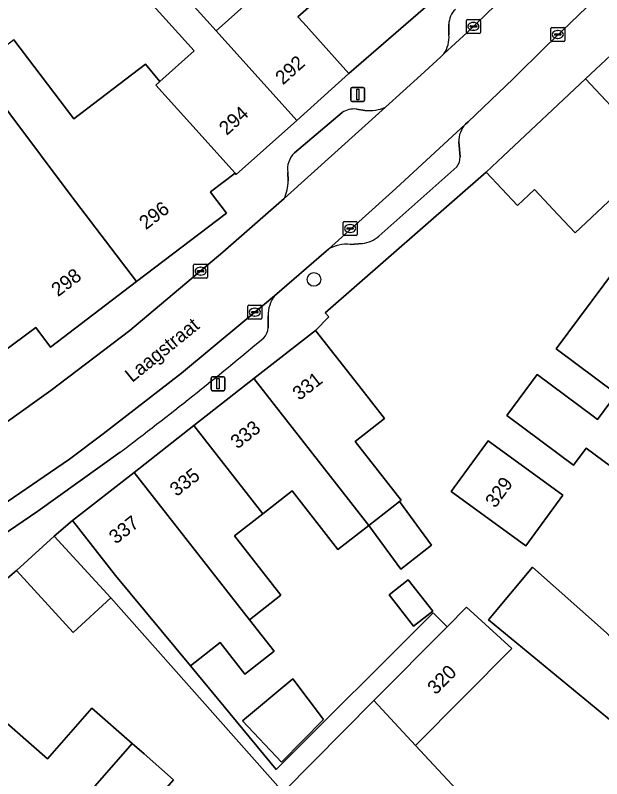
# Model space of a CAD drawing. Extents: x 159217 to 160349, y 381246 to 382172.
# Drawn here: x 160127.1 to 160169.1, y 381674.9 to 381729.7 of the extents above; entities that cross this region are included whole.
import ezdxf

# ---------------------------------------------------------------- set-up
doc = ezdxf.new("R2010")
doc.units = 0
for name, color, linetype in [('IMGEO_Boom', 7, 'Continuous'), ('IMGEO_Erf', 7, 'Continuous'), ('IMGEO_Kolk', 7, 'Continuous'), ('IMGEO_Lichtmast', 7, 'Continuous'), ('IMGEO_Muur', 7, 'Continuous'), ('IMGEO_Openbare_ruimte_label', 7, 'Continuous'), ('IMGEO_Pand', 7, 'Continuous'), ('IMGEO_Pand_nummerreeks', 7, 'Continuous'), ('IMGEO_Parkeervlak_open', 7, 'Continuous'), ('IMGEO_Rijbaan_lokaal_open', 7, 'Continuous'), ('IMGEO_Rioolput', 7, 'Continuous'), ('IMGEO_Voetpad_open', 7, 'Continuous')]:
    doc.layers.add(name, color=color, linetype=linetype)

msp = doc.modelspace()

# ---------------------------------------------------------------- linework, layer by layer
at = {"layer": 'IMGEO_Boom'}
msp.add_circle((160148.48, 381710.751), 0.489, dxfattribs=at)
at = {"layer": 'IMGEO_Erf'}
for points in [[(160137.869, 381732.584), (160141.47, 381728.578), (160145.218, 381731.947)], [(160126.951, 381727.928), (160131.256, 381722.282), (160136.388, 381726.195), (160137.421, 381724.939), (160139.884, 381727.152), (160136.283, 381731.159)], [(160148.841, 381730.954), (160147.331, 381729.597), (160147.702, 381729.183), (160150.987, 381725.528), (160157.187, 381730.928)], [(160173.124, 381719.643), (160167.213, 381714.092), (160165.619, 381715.789), (160165.324, 381716.104), (160164.296, 381717.197), (160163.082, 381716.057), (160160.843, 381718.441), (160149.291, 381708.343), (160149.538, 381708.06), (160148.586, 381707.09), (160151.668, 381703.153), (160153.538, 381700.763), (160151.432, 381699.115), (160154.727, 381694.905), (160154.607, 381694.811), (160156.916, 381691.674), (160154.72, 381689.956), (160152.415, 381693.096), (160150.201, 381691.363), (160146.906, 381695.573), (160144.82, 381693.941), (160142.78, 381692.344), (160146.106, 381688.095), (160143.848, 381686.327), (160145.614, 381684.072), (160143.526, 381682.437), (160141.76, 381684.692), (160139.617, 381683.014), (160145.774, 381675.588), (160157.031, 381686.822), (160158.032, 381685.832), (160159.421, 381687.235), (160162.664, 381684.257), (160155.774, 381677.313), (160168.856, 381663.241)], [(160133.914, 381687.899), (160131.201, 381685.415), (160127.136, 381689.854), (160120.973, 381684.618)], [(160174.403, 381675.265), (160160.99, 381686.315), (160164.149, 381690.107), (160169.471, 381685.396)], [(160121.119, 381682.46), (160121.665, 381683.084), (160125.837, 381679.432), (160129.356, 381676.353), (160132.541, 381679.993), (160135.449, 381677.448), (160136.304, 381676.7), (160138.411, 381674.855), (160135.236, 381671.227), (160138.683, 381668.21), (160141.867, 381671.847), (160143.661, 381670.277), (160140.478, 381666.64), (160142.616, 381664.769), (160148.269, 381671.336), (160145.952, 381673.63), (160146.273, 381673.954), (160133.914, 381687.899)]]:
    msp.add_lwpolyline(points, dxfattribs=at)
for points in [[(160179.535, 381706.233), (160183.549, 381703.251), (160175.817, 381692.844), (160168.008, 381698.646), (160167.1, 381697.424), (160162.304, 381700.987), (160164.487, 381703.924), (160168.5, 381700.942), (160168.821, 381700.704), (160170.183, 381702.538), (160165.85, 381705.758), (160170.946, 381712.616), (160175.279, 381709.396)], [(160166.323, 381695.265), (160163.671, 381691.626), (160158.322, 381695.523), (160160.975, 381699.163)], [(160153.87, 381688.122), (160155.246, 381689.198), (160156.999, 381686.957), (160155.624, 381685.881)], [(160143.347, 381679.066), (160146.967, 381682.092), (160149.172, 381679.183), (160146.155, 381676.119)]]:
    msp.add_lwpolyline(points, close=True, dxfattribs=at)
at = {"layer": 'IMGEO_Kolk'}
for p, q in [((160159.415, 381728.477), (160159.415, 381729.329)), ((160159.49, 381729.403), (160160.342, 381729.403)), ((160160.416, 381729.329), (160160.416, 381728.477)), ((160159.674, 381728.897), (160159.674, 381728.909)), ((160160.112, 381728.86), (160159.714, 381728.86)), ((160159.717, 381728.946), (160160.115, 381728.946)), ((160159.903, 381729.183), (160159.928, 381729.183)), ((160160.158, 381728.909), (160160.158, 381728.897)), ((160165.469, 381727.896), (160165.469, 381728.748)), ((160165.544, 381728.822), (160166.396, 381728.822)), ((160166.47, 381728.748), (160166.47, 381727.896)), ((160160.342, 381728.403), (160159.49, 381728.403)), ((160159.926, 381728.623), (160159.901, 381728.623)), ((160165.728, 381728.316), (160165.728, 381728.328)), ((160166.166, 381728.279), (160165.768, 381728.279)), ((160165.771, 381728.365), (160166.169, 381728.365)), ((160165.957, 381728.602), (160165.982, 381728.602)), ((160166.212, 381728.328), (160166.212, 381728.316)), ((160166.396, 381727.822), (160165.544, 381727.822)), ((160165.98, 381728.042), (160165.955, 381728.042)), ((160139.848, 381710.911), (160139.848, 381711.763)), ((160139.923, 381711.837), (160140.775, 381711.837)), ((160140.849, 381711.763), (160140.849, 381710.911)), ((160140.107, 381711.331), (160140.107, 381711.343)), ((160140.545, 381711.294), (160140.147, 381711.294)), ((160140.15, 381711.38), (160140.548, 381711.38)), ((160140.336, 381711.617), (160140.361, 381711.617)), ((160140.591, 381711.343), (160140.591, 381711.331)), ((160140.775, 381710.837), (160139.923, 381710.837)), ((160140.359, 381711.057), (160140.334, 381711.057)), ((160143.738, 381707.974), (160143.738, 381708.826)), ((160143.813, 381708.9), (160144.665, 381708.9)), ((160144.226, 381708.68), (160144.251, 381708.68)), ((160144.739, 381708.826), (160144.739, 381707.974)), ((160143.997, 381708.394), (160143.997, 381708.406)), ((160144.435, 381708.357), (160144.037, 381708.357)), ((160144.04, 381708.443), (160144.438, 381708.443)), ((160144.249, 381708.12), (160144.224, 381708.12)), ((160144.481, 381708.406), (160144.481, 381708.394)), ((160144.665, 381707.9), (160143.813, 381707.9))]:
    msp.add_line(p, q, dxfattribs=at)
for points in [[(160159.415, 381728.477), (160159.415, 381729.329)], [(160159.49, 381729.403), (160160.342, 381729.403)], [(160160.416, 381729.329), (160160.416, 381728.477)], [(160165.469, 381727.896), (160165.469, 381728.748)], [(160165.544, 381728.822), (160166.396, 381728.822)], [(160166.47, 381728.748), (160166.47, 381727.896)], [(160160.342, 381728.403), (160159.49, 381728.403)], [(160166.396, 381727.822), (160165.544, 381727.822)], [(160139.848, 381710.911), (160139.848, 381711.763)], [(160139.923, 381711.837), (160140.775, 381711.837)], [(160140.849, 381711.763), (160140.849, 381710.911)], [(160140.775, 381710.837), (160139.923, 381710.837)], [(160143.738, 381707.974), (160143.738, 381708.826)], [(160143.813, 381708.9), (160144.665, 381708.9)], [(160144.739, 381708.826), (160144.739, 381707.974)], [(160144.665, 381707.9), (160143.813, 381707.9)]]:
    msp.add_lwpolyline(points, dxfattribs=at)
for centre, radius, start, end in [((160159.492, 381729.327), 0.0765, 91.552, 178.448), ((160159.492, 381729.327), 0.0765, 91.552, 178.448), ((160160.34, 381729.327), 0.0765, 1.552, 88.448), ((160160.34, 381729.327), 0.0765, 1.552, 88.448), ((160159.714, 381728.906), 0.0403, 85.8775, 175.7526), ((160159.711, 381728.896), 0.0366, 178.938, 274.7102), ((160160.115, 381728.903), 0.043, 264.8664, 352.4533), ((160160.119, 381728.908), 0.0386, 1.7309, 96.639), ((160165.546, 381728.746), 0.0765, 91.552, 178.448), ((160165.546, 381728.746), 0.0765, 91.552, 178.448), ((160166.394, 381728.746), 0.0765, 1.552, 88.448), ((160166.394, 381728.746), 0.0765, 1.552, 88.448), ((160159.492, 381728.479), 0.0765, 181.552, 268.448), ((160159.492, 381728.479), 0.0765, 181.552, 268.448), ((160160.34, 381728.479), 0.0765, 271.552, 358.448), ((160160.34, 381728.479), 0.0765, 271.552, 358.448), ((160165.768, 381728.325), 0.0403, 85.8775, 175.7526), ((160165.765, 381728.315), 0.0366, 178.938, 274.7102), ((160166.169, 381728.322), 0.043, 264.8664, 352.4533), ((160166.173, 381728.327), 0.0386, 1.7309, 96.639), ((160165.546, 381727.898), 0.0765, 181.552, 268.448), ((160165.546, 381727.898), 0.0765, 181.552, 268.448), ((160166.394, 381727.898), 0.0765, 271.552, 358.448), ((160166.394, 381727.898), 0.0765, 271.552, 358.448), ((160139.925, 381711.761), 0.0765, 91.552, 178.448), ((160139.925, 381711.761), 0.0765, 91.552, 178.448), ((160140.773, 381711.761), 0.0765, 1.552, 88.448), ((160140.773, 381711.761), 0.0765, 1.552, 88.448), ((160140.147, 381711.34), 0.0403, 85.8775, 175.7526), ((160140.144, 381711.33), 0.0366, 178.938, 274.7102), ((160140.548, 381711.337), 0.043, 264.8664, 352.4533), ((160140.552, 381711.342), 0.0386, 1.7309, 96.639), ((160139.925, 381710.913), 0.0765, 181.552, 268.448), ((160139.925, 381710.913), 0.0765, 181.552, 268.448), ((160140.773, 381710.913), 0.0765, 271.552, 358.448), ((160140.773, 381710.913), 0.0765, 271.552, 358.448), ((160143.815, 381708.824), 0.0765, 91.552, 178.448), ((160143.815, 381708.824), 0.0765, 91.552, 178.448), ((160144.663, 381708.824), 0.0765, 1.552, 88.448), ((160144.663, 381708.824), 0.0765, 1.552, 88.448), ((160143.815, 381707.976), 0.0765, 181.552, 268.448), ((160143.815, 381707.976), 0.0765, 181.552, 268.448), ((160144.037, 381708.403), 0.0403, 85.8775, 175.7526), ((160144.034, 381708.393), 0.0366, 178.938, 274.7102), ((160144.438, 381708.4), 0.043, 264.8664, 352.4533), ((160144.442, 381708.405), 0.0386, 1.7309, 96.639), ((160144.663, 381707.976), 0.0765, 271.552, 358.448), ((160144.663, 381707.976), 0.0765, 271.552, 358.448)]:
    msp.add_arc(centre, radius, start, end, dxfattribs=at)
for centre, major_axis, ratio, start_param, end_param in [((160159.902, 381728.903), (-0.387, 0.002), 0.722429, 4.712389, 7.853982), ((160159.927, 381728.903), (-0.39, 0.002), 0.717154, 1.570796, 4.712389), ((160165.956, 381728.322), (-0.387, 0.002), 0.722429, 4.712389, 7.853982), ((160165.981, 381728.322), (-0.39, 0.002), 0.717154, 1.570796, 4.712389), ((160140.335, 381711.337), (-0.387, 0.002), 0.722429, 4.712389, 7.853982), ((160140.36, 381711.337), (-0.39, 0.002), 0.717154, 1.570796, 4.712389), ((160144.225, 381708.4), (-0.387, 0.002), 0.722429, 4.712389, 7.853982), ((160144.25, 381708.4), (-0.39, 0.002), 0.717154, 1.570796, 4.712389)]:
    msp.add_ellipse(centre, major_axis=major_axis, ratio=ratio, start_param=start_param, end_param=end_param, dxfattribs=at)
at = {"layer": 'IMGEO_Lichtmast'}
for p, q in [((160151.123, 381723.616), (160151.123, 381724.416)), ((160151.123, 381724.416), (160151.123, 381723.616)), ((160151.223, 381724.516), (160152.013, 381724.516)), ((160152.013, 381724.516), (160151.223, 381724.516)), ((160152.113, 381724.416), (160152.113, 381723.616)), ((160152.113, 381723.616), (160152.113, 381724.416)), ((160152.013, 381723.516), (160151.223, 381723.516)), ((160151.223, 381723.516), (160152.013, 381723.516)), ((160141.098, 381702.863), (160141.098, 381703.663)), ((160141.098, 381703.663), (160141.098, 381702.863)), ((160141.198, 381703.763), (160141.988, 381703.763)), ((160141.988, 381703.763), (160141.198, 381703.763)), ((160142.088, 381703.663), (160142.088, 381702.863)), ((160142.088, 381702.863), (160142.088, 381703.663)), ((160141.988, 381702.763), (160141.198, 381702.763)), ((160141.198, 381702.763), (160141.988, 381702.763))]:
    msp.add_line(p, q, dxfattribs=at)
for points in [[(160151.543, 381724.391), (160151.693, 381724.391), (160151.693, 381723.641), (160151.543, 381723.641), (160151.543, 381724.391)], [(160141.518, 381703.638), (160141.668, 381703.638), (160141.668, 381702.888), (160141.518, 381702.888), (160141.518, 381703.638)]]:
    msp.add_lwpolyline(points, dxfattribs=at)
for centre, start, end in [((160151.223, 381724.416), 90, 180), ((160151.223, 381724.416), 90, 180), ((160152.013, 381724.416), 0, 90), ((160152.013, 381724.416), 360, 90), ((160151.223, 381723.616), 180, 270), ((160151.223, 381723.616), 180, 270), ((160152.013, 381723.616), 270, 0), ((160152.013, 381723.616), 270, 0), ((160141.198, 381703.663), 90, 180), ((160141.198, 381703.663), 90, 180), ((160141.988, 381703.663), 0, 90), ((160141.988, 381703.663), 360, 90), ((160141.198, 381702.863), 180, 270), ((160141.198, 381702.863), 180, 270), ((160141.988, 381702.863), 270, 0), ((160141.988, 381702.863), 270, 0)]:
    msp.add_arc(centre, 0.1, start, end, dxfattribs=at)
at = {"layer": 'IMGEO_Muur'}
msp.add_lwpolyline([(160149.291, 381708.343), (160160.843, 381718.441)], dxfattribs=at)
at = {"layer": 'IMGEO_Pand'}
for points in [[(160147.239, 381722.16), (160150.987, 381725.528), (160147.702, 381729.183), (160147.331, 381729.597), (160148.841, 381730.954), (160148.373, 381731.474), (160146.729, 381733.305), (160145.218, 381731.947), (160141.47, 381728.578)], [(160141.47, 381728.578), (160137.869, 381732.584), (160136.283, 381731.159), (160139.884, 381727.152), (160137.421, 381724.939), (160137.14, 381724.686), (160139.566, 381721.987), (160142.817, 381718.37), (160142.909, 381718.268), (160147.239, 381722.16)], [(160178.106, 381722.006), (160175.38, 381724.941), (160174.53, 381724.688), (160171.233, 381728.199), (160167.968, 381725.132), (160171.234, 381721.655), (160173.124, 381719.643), (160177.663, 381715.301), (160179.986, 381713.17), (160181.671, 381714.718), (160179.519, 381717.044), (160176.38, 381720.386)], [(160137.421, 381724.939), (160136.388, 381726.195), (160131.256, 381722.282), (160126.951, 381727.928), (160124.231, 381725.854), (160124.515, 381725.478), (160130.98, 381716.839), (160135.744, 381710.589), (160142.201, 381715.512), (160141.127, 381716.921), (160141.049, 381717.023), (160142.817, 381718.37), (160139.566, 381721.987), (160137.14, 381724.686)], [(160124.515, 381725.478), (160122.372, 381723.844), (160126.11, 381715.777), (160122.913, 381713.339), (160120.192, 381716.91), (160116.892, 381714.433), (160119.122, 381711.508), (160120.126, 381710.191), (160124.594, 381704.402), (160128.518, 381707.294), (160129.585, 381705.894), (160135.744, 381710.589), (160130.98, 381716.839)], [(160167.968, 381725.132), (160162.057, 381719.581), (160160.843, 381718.441), (160163.082, 381716.057), (160164.296, 381717.197), (160165.324, 381716.104), (160165.619, 381715.789), (160167.213, 381714.092), (160173.124, 381719.643), (160171.234, 381721.655)], [(160175.279, 381709.396), (160170.946, 381712.616), (160165.85, 381705.758), (160170.183, 381702.538), (160168.821, 381700.704), (160168.5, 381700.942), (160164.487, 381703.924), (160162.304, 381700.987), (160167.1, 381697.424), (160168.008, 381698.646), (160175.817, 381692.844), (160183.549, 381703.251), (160179.535, 381706.233)], [(160153.538, 381700.763), (160151.668, 381703.153), (160148.586, 381707.09), (160144.167, 381703.631), (160152.415, 381693.096), (160154.607, 381694.811), (160154.727, 381694.905), (160151.432, 381699.115)], [(160144.167, 381703.631), (160139.868, 381700.266), (160144.82, 381693.941), (160146.906, 381695.573), (160150.201, 381691.363), (160152.415, 381693.096)], [(160135.57, 381696.901), (160143.848, 381686.327), (160146.106, 381688.095), (160142.78, 381692.344), (160144.82, 381693.941), (160139.868, 381700.266)], [(160163.671, 381691.626), (160166.323, 381695.265), (160160.975, 381699.163), (160158.322, 381695.523)], [(160135.57, 381696.901), (160131.153, 381693.444), (160134.234, 381689.507), (160139.617, 381683.014), (160141.76, 381684.692), (160143.526, 381682.437), (160145.614, 381684.072), (160143.848, 381686.327)], [(160154.607, 381694.811), (160152.415, 381693.096), (160154.72, 381689.956), (160156.916, 381691.674)], [(160129.85, 381692.338), (160127.136, 381689.854), (160131.201, 381685.415), (160133.914, 381687.899)], [(160174.403, 381675.265), (160176.563, 381679.334), (160172.975, 381681.622), (160169.471, 381685.396), (160164.149, 381690.107), (160160.99, 381686.315)], [(160153.87, 381688.122), (160155.624, 381685.881), (160156.999, 381686.957), (160155.246, 381689.198)], [(160162.664, 381684.257), (160159.421, 381687.235), (160158.032, 381685.832), (160152.783, 381680.53), (160155.774, 381677.313)], [(160143.347, 381679.066), (160146.155, 381676.119), (160149.172, 381679.183), (160146.967, 381682.092)], [(160155.774, 381677.313), (160152.783, 381680.53), (160146.273, 381673.954), (160145.952, 381673.63), (160148.269, 381671.336), (160149.78, 381669.84), (160153.351, 381666.306), (160154.45, 381665.218), (160154.626, 381665.044), (160169.728, 381650.105), (160175.686, 381656.21), (160175.82, 381656.347), (160172.267, 381659.865), (160168.856, 381663.241)], [(160135.449, 381677.448), (160132.541, 381679.993), (160129.356, 381676.353), (160125.837, 381679.432), (160119.569, 381672.267), (160123.744, 381668.613), (160126.21, 381671.431), (160127.864, 381673.32), (160130.112, 381671.353)], [(160135.449, 381677.448), (160130.112, 381671.353), (160132.359, 381669.386), (160130.705, 381667.497), (160128.222, 381664.659), (160132.385, 381661.015), (160138.683, 381668.21), (160135.236, 381671.227), (160138.411, 381674.855), (160136.304, 381676.7)]]:
    msp.add_lwpolyline(points, close=True, dxfattribs=at)
at = {"layer": 'IMGEO_Parkeervlak_open'}
for points in [[(160157.801, 381726.925), (160158.638, 381727.698), (160159.473, 381728.475), (160164.834, 381733.645)], [(160158.153, 381729.067), (160158.165, 381728.305)], [(160146.337, 381716.559), (160153.618, 381723.101)], [(160150.499, 381722.724), (160147.072, 381719.827)], [(160152.139, 381722.879), (160151.521, 381722.972)], [(160159.358, 381721.892), (160154.354, 381717.264), (160149.512, 381712.923)], [(160158.961, 381719.534), (160158.868, 381720.612)], [(160146.595, 381718.43), (160146.621, 381717.815)], [(160153.132, 381713.86), (160158.72, 381718.835)], [(160151.088, 381713.264), (160151.951, 381713.327)], [(160145.656, 381709.578), (160138.973, 381704.025), (160133.365, 381699.681), (160130.946, 381697.856), (160126.471, 381694.798)], [(160145.195, 381707.275), (160145.198, 381708.144)], [(160125.071, 381691.69), (160125.569, 381692.02), (160128.673, 381694.12), (160134.581, 381698.352)]]:
    msp.add_lwpolyline(points, dxfattribs=at)
for centre, radius, start, end in [((160159.668, 381729.022), 1.516, 133.5928, 178.3006), ((160155.952, 381728.151), 2.219, 326.4635, 3.984), ((160151.382, 381721.316), 1.661, 85.1897, 122.09), ((160152.444, 381725.882), 3.018, 264.1917, 292.8812), ((160160.649, 381720.664), 1.782, 136.4327, 181.6724), ((160148.207, 381718.66), 1.628, 134.1867, 188.1088), ((160157.97, 381719.484), 0.992, 319.0925, 2.8613), ((160143.946, 381717.76), 2.676, 333.3364, 1.1813), ((160151.748, 381715.352), 2.035, 275.7313, 312.8492), ((160150.859, 381710.508), 2.766, 85.2594, 119.1584), ((160147.415, 381708.226), 2.218, 142.452, 182.1225), ((160143.982, 381707.374), 1.217, 317.4156, 355.3505), ((159974.31, 381910.224), 265.662, 307.10573, 309.94467)]:
    msp.add_arc(centre, radius, start, end, dxfattribs=at)
at = {"layer": 'IMGEO_Rijbaan_lokaal_open'}
for points in [[(160164.834, 381733.645), (160159.473, 381728.475), (160158.638, 381727.698), (160157.801, 381726.925), (160157.584, 381726.725), (160156.149, 381725.405), (160153.618, 381723.101), (160146.337, 381716.559), (160145.396, 381715.724), (160141.947, 381712.707), (160135.275, 381707.086), (160129.595, 381702.78), (160126.504, 381700.563), (160126.067, 381700.256), (160125.075, 381699.567), (160124.08, 381698.883)], [(160145.656, 381709.578), (160149.355, 381712.771), (160149.512, 381712.923), (160154.354, 381717.264), (160159.358, 381721.892), (160159.543, 381722.044), (160162.775, 381725.141), (160165.135, 381727.494), (160168.6, 381730.835)], [(160126.471, 381694.798), (160130.946, 381697.856), (160133.365, 381699.681), (160138.973, 381704.025), (160145.656, 381709.578)]]:
    msp.add_lwpolyline(points, dxfattribs=at)
at = {"layer": 'IMGEO_Rioolput'}
for p, q in [((160150.574, 381713.975), (160150.574, 381714.827)), ((160150.649, 381714.901), (160151.501, 381714.901)), ((160151.062, 381714.681), (160151.087, 381714.681)), ((160151.575, 381714.827), (160151.575, 381713.975)), ((160150.833, 381714.395), (160150.833, 381714.407)), ((160151.271, 381714.358), (160150.873, 381714.358)), ((160150.876, 381714.444), (160151.274, 381714.444)), ((160151.085, 381714.121), (160151.06, 381714.121)), ((160151.317, 381714.407), (160151.317, 381714.395)), ((160151.501, 381713.901), (160150.649, 381713.901))]:
    msp.add_line(p, q, dxfattribs=at)
for points in [[(160150.574, 381713.975), (160150.574, 381714.827)], [(160150.649, 381714.901), (160151.501, 381714.901)], [(160151.575, 381714.827), (160151.575, 381713.975)], [(160151.501, 381713.901), (160150.649, 381713.901)]]:
    msp.add_lwpolyline(points, dxfattribs=at)
for centre, radius, start, end in [((160150.651, 381714.825), 0.0765, 91.552, 178.448), ((160150.651, 381714.825), 0.0765, 91.552, 178.448), ((160151.499, 381714.825), 0.0765, 1.552, 88.448), ((160151.499, 381714.825), 0.0765, 1.552, 88.448), ((160150.651, 381713.977), 0.0765, 181.552, 268.448), ((160150.651, 381713.977), 0.0765, 181.552, 268.448), ((160150.873, 381714.404), 0.0403, 85.8775, 175.7526), ((160150.87, 381714.394), 0.0366, 178.938, 274.7102), ((160151.274, 381714.401), 0.043, 264.8664, 352.4533), ((160151.278, 381714.406), 0.0386, 1.7309, 96.639), ((160151.499, 381713.977), 0.0765, 271.552, 358.448), ((160151.499, 381713.977), 0.0765, 271.552, 358.448)]:
    msp.add_arc(centre, radius, start, end, dxfattribs=at)
for centre, major_axis, ratio, start_param, end_param in [((160151.061, 381714.401), (-0.387, 0.002), 0.722429, 4.712389, 7.853982), ((160151.086, 381714.401), (-0.39, 0.002), 0.717154, 1.570796, 4.712389)]:
    msp.add_ellipse(centre, major_axis=major_axis, ratio=ratio, start_param=start_param, end_param=end_param, dxfattribs=at)
at = {"layer": 'IMGEO_Voetpad_open'}
for points in [[(160176.84, 381740.236), (160173.087, 381735.575), (160172.471, 381734.902), (160168.6, 381730.835), (160165.135, 381727.494), (160162.775, 381725.141), (160159.543, 381722.044), (160159.358, 381721.892)], [(160157.187, 381730.928), (160150.987, 381725.528), (160147.239, 381722.16), (160142.909, 381718.268), (160142.817, 381718.37), (160141.049, 381717.023), (160141.127, 381716.921), (160142.201, 381715.512), (160135.744, 381710.589), (160129.585, 381705.894), (160128.518, 381707.294), (160124.594, 381704.402), (160119.766, 381701.128), (160115.549, 381698.268), (160111.212, 381695.327), (160106.671, 381692.247), (160105.798, 381691.686), (160102.628, 381689.536), (160099.526, 381687.617), (160096.39, 381685.677), (160098.529, 381683.565)], [(160158.165, 381728.305), (160158.153, 381729.067)], [(160120.973, 381684.618), (160127.136, 381689.854), (160129.85, 381692.338), (160131.153, 381693.444), (160135.57, 381696.901), (160139.868, 381700.266), (160144.167, 381703.631), (160148.586, 381707.09), (160149.538, 381708.06), (160149.291, 381708.343), (160160.843, 381718.441), (160162.057, 381719.581), (160167.968, 381725.132), (160171.233, 381728.199)], [(160153.618, 381723.101), (160156.149, 381725.405), (160157.584, 381726.725), (160157.801, 381726.925)], [(160147.072, 381719.827), (160150.499, 381722.724)], [(160151.521, 381722.972), (160152.139, 381722.879)], [(160158.868, 381720.612), (160158.961, 381719.534)], [(160146.621, 381717.815), (160146.595, 381718.43)], [(160158.72, 381718.835), (160153.132, 381713.86)], [(160126.067, 381700.256), (160126.504, 381700.563), (160129.595, 381702.78), (160135.275, 381707.086), (160141.947, 381712.707), (160145.396, 381715.724), (160146.337, 381716.559)], [(160149.512, 381712.923), (160149.355, 381712.771), (160145.656, 381709.578)], [(160151.951, 381713.327), (160151.088, 381713.264)], [(160145.198, 381708.144), (160145.195, 381707.275)], [(160134.581, 381698.352), (160128.673, 381694.12), (160125.569, 381692.02), (160125.071, 381691.69)]]:
    msp.add_lwpolyline(points, dxfattribs=at)
msp.add_lwpolyline([(160139.617, 381683.014), (160134.234, 381689.507), (160131.153, 381693.444), (160129.85, 381692.338), (160133.914, 381687.899), (160146.273, 381673.954), (160152.783, 381680.53), (160158.032, 381685.832), (160157.031, 381686.822), (160145.774, 381675.588)], close=True, dxfattribs=at)
for centre, radius, start, end in [((160159.668, 381729.022), 1.516, 133.5928, 178.3006), ((160155.952, 381728.151), 2.219, 326.4635, 3.984), ((160151.382, 381721.316), 1.661, 85.1897, 122.09), ((160152.444, 381725.882), 3.018, 264.1917, 292.8812), ((160160.649, 381720.664), 1.782, 136.4327, 181.6724), ((160148.207, 381718.66), 1.628, 134.1867, 188.1088), ((160157.97, 381719.484), 0.992, 319.0925, 2.8613), ((160143.946, 381717.76), 2.676, 333.3364, 1.1813), ((160151.748, 381715.352), 2.035, 275.7313, 312.8492), ((160150.859, 381710.508), 2.766, 85.2594, 119.1584), ((160147.415, 381708.226), 2.218, 142.452, 182.1225), ((160143.982, 381707.374), 1.217, 317.4156, 355.3505), ((159974.31, 381910.224), 265.662, 307.10573, 309.94467)]:
    msp.add_arc(centre, radius, start, end, dxfattribs=at)

# ---------------------------------------------------------------- texts
at = {"layer": 'IMGEO_Openbare_ruimte_label'}
msp.add_text('Laagstraat', height=1, rotation=39.0355, dxfattribs=at).set_placement((160135.435, 381703.314))
at = {"layer": 'IMGEO_Pand_nummerreeks'}
for s, rotation, p in [('292', 41.9472, (160146.256, 381724.664)), ('294', 41.9462, (160142.22, 381721.036)), ('296', 37.3225, (160136.423, 381714.276)), ('298', 37.3225, (160130.118, 381709.469)), ('331', 38.0501, (160147.432, 381702.021)), ('333', 38.0527, (160142.985, 381698.541)), ('335', 38.0527, (160138.627, 381695.13)), ('329', 53.9137, (160161.487, 381694.297)), ('337', 38.0501, (160134.269, 381691.717)), ('320', 45.023, (160157.21, 381680.897))]:
    msp.add_text(s, height=1, rotation=rotation, dxfattribs=at).set_placement(p)

doc.saveas('drawing.dxf')
